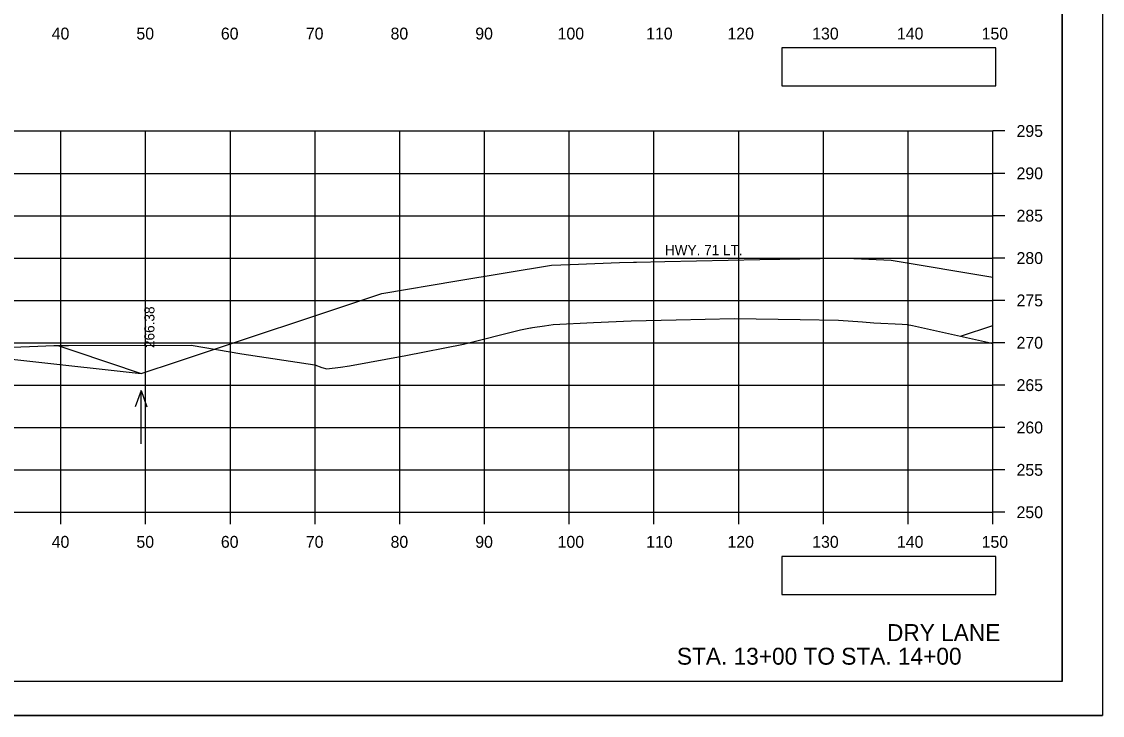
# Model space of a CAD drawing. Extents: x 285 to 4233, y -659 to 3710.
# Drawn here: x 4105.7 to 4233.3, y -365.9 to -284 of the extents above; entities that cross this region are included whole.
import ezdxf

# ---------------------------------------------------------------- set-up
doc = ezdxf.new("R2010")
doc.units = 0
for name, color, linetype in [('R_Axis', 7, 'Continuous'), ('R_Axis Annot', 7, 'Continuous'), ('R_Border', 7, 'Continuous'), ('R_Draft', 7, 'Continuous'), ('R_Exist Surface', 7, 'Continuous'), ('R_Fin Surface', 7, 'Continuous'), ('R_Grid', 7, 'Continuous'), ('R_No Plot', 7, 'Continuous'), ('R_Water', 7, 'Continuous'), ('R_Water Annot', 7, 'Continuous'), ('R_Xsect Elev', 7, 'Continuous')]:
    doc.layers.add(name, color=color, linetype=linetype)

msp = doc.modelspace()

# ---------------------------------------------------------------- linework, layer by layer
at = {"layer": 'R_Axis'}
for p, q in [((4220.38, -341.92), (4220.38, -296.92)), ((4221.78, -296.92), (4220.38, -296.92)), ((4221.78, -301.92), (4220.38, -301.92)), ((4221.78, -306.92), (4220.38, -306.92)), ((4221.78, -311.92), (4220.38, -311.92)), ((4221.78, -316.92), (4220.38, -316.92)), ((4221.78, -321.92), (4220.38, -321.92)), ((4221.78, -326.92), (4220.38, -326.92)), ((4221.78, -331.92), (4220.38, -331.92)), ((4221.78, -336.92), (4220.38, -336.92)), ((3920.38, -341.92), (4220.38, -341.92)), ((4110.38, -343.32), (4110.38, -341.92)), ((4120.38, -343.32), (4120.38, -341.92)), ((4130.38, -343.32), (4130.38, -341.92)), ((4140.38, -343.32), (4140.38, -341.92)), ((4150.38, -343.32), (4150.38, -341.92)), ((4160.38, -343.32), (4160.38, -341.92)), ((4170.38, -343.32), (4170.38, -341.92)), ((4180.38, -343.32), (4180.38, -341.92)), ((4190.38, -343.32), (4190.38, -341.92)), ((4200.38, -343.32), (4200.38, -341.92)), ((4210.38, -343.32), (4210.38, -341.92)), ((4220.38, -343.32), (4220.38, -341.92)), ((4221.78, -341.92), (4220.38, -341.92))]:
    msp.add_line(p, q, dxfattribs=at)
at = {"layer": 'R_Axis Annot'}
for points in [[(4195.48, -291.58), (4220.73, -291.58), (4220.73, -287.11), (4195.48, -287.11)], [(4195.48, -351.62), (4220.73, -351.62), (4220.73, -347.15), (4195.48, -347.15)]]:
    msp.add_lwpolyline(points, close=True, dxfattribs=at)
at = {"layer": 'R_Border'}
for q in [(4228.56, -156.46), (3912.38, -361.92)]:
    msp.add_line((4228.56, -361.92), q, dxfattribs=at)
at = {"layer": 'R_Exist Surface'}
msp.add_lwpolyline([(4099.62, -322.62), (4107.65, -322.33), (4109.55, -322.25), (4111.29, -322.25), (4125.74, -322.2), (4131.72, -323.24), (4140.36, -324.53), (4141.18, -324.83), (4141.76, -325.01), (4143.37, -324.81), (4144.46, -324.65), (4151.1, -323.41), (4157.9, -322.08), (4164.64, -320.4), (4165.8, -320.14), (4165.87, -320.14), (4166.03, -320.11), (4167.47, -319.91), (4168.47, -319.77), (4173.24, -319.54), (4177.69, -319.34), (4183.01, -319.21), (4189.83, -319.04), (4197.64, -319.18), (4202.18, -319.26), (4204.98, -319.46), (4206.32, -319.56), (4209.69, -319.74), (4210.28, -319.78), (4210.89, -319.89), (4219.77, -321.83), (4220.38, -321.99)], dxfattribs=at)
at = {"layer": 'R_Fin Surface'}
for points in [[(4110.02, -322.25), (4112.01, -322.92), (4119.87, -325.54), (4124.13, -324.12), (4148.26, -316.09), (4157.12, -314.62), (4168.3, -312.76), (4170.51, -312.67), (4176.31, -312.44), (4177.95, -312.41), (4178.31, -312.4), (4181.65, -312.33), (4192.86, -312.11), (4202.36, -311.92), (4203.12, -311.95), (4208.37, -312.16), (4220.38, -314.16)], [(4216.58, -321.14), (4220.38, -319.87)], [(4038.85, -328.34), (4060.38, -321.16), (4070.38, -320.96), (4080.38, -321.16), (4119.87, -325.54)]]:
    msp.add_lwpolyline(points, dxfattribs=at)
at = {"layer": 'R_Grid'}
for p, q in [((3920.38, -296.92), (4220.38, -296.92)), ((4110.38, -341.92), (4110.38, -296.92)), ((4120.38, -341.92), (4120.38, -296.92)), ((4130.38, -341.92), (4130.38, -296.92)), ((4140.38, -341.92), (4140.38, -296.92)), ((4150.38, -341.92), (4150.38, -296.92)), ((4160.38, -341.92), (4160.38, -296.92)), ((4170.38, -341.92), (4170.38, -296.92)), ((4180.38, -341.92), (4180.38, -296.92)), ((4190.38, -341.92), (4190.38, -296.92)), ((4200.38, -341.92), (4200.38, -296.92)), ((4210.38, -341.92), (4210.38, -296.92)), ((4220.38, -341.92), (4220.38, -296.92)), ((3920.38, -301.92), (4220.38, -301.92)), ((3920.38, -306.92), (4220.38, -306.92)), ((3920.38, -311.92), (4220.38, -311.92)), ((3920.38, -316.92), (4220.38, -316.92)), ((3920.38, -321.92), (4220.38, -321.92)), ((3920.38, -326.92), (4220.38, -326.92)), ((3920.38, -331.92), (4220.38, -331.92)), ((3920.38, -336.92), (4220.38, -336.92)), ((3920.38, -341.92), (4220.38, -341.92))]:
    msp.add_line(p, q, dxfattribs=at)
at = {"layer": 'R_No Plot'}
msp.add_line((3899.98, -365.9), (4233.31, -365.9), dxfattribs=at)
for points in [[(3899.97, -152.57), (4233.31, -152.57), (4233.31, -365.9), (3899.97, -365.9)], [(4146.3, -156.46), (4165.92, -156.46), (4165.92, -166.34), (4182.03, -166.34), (4205.23, -166.34), (4205.35, -194.5), (4228.56, -194.5), (4228.56, -361.92), (3912.38, -361.92), (3912.38, -156.46)]]:
    msp.add_lwpolyline(points, close=True, dxfattribs=at)
at = {"layer": 'R_Water Annot'}
for p, q in [((4119.84, -327.56), (4119.14, -329.48)), ((4119.84, -333.85), (4119.84, -327.56)), ((4119.84, -327.56), (4120.54, -329.48))]:
    msp.add_line(p, q, dxfattribs=at)

# ---------------------------------------------------------------- texts
at = {"layer": 'R_Axis Annot'}
for s, p in [('40', (4109.29, -286.12)), ('50', (4119.29, -286.12)), ('60', (4129.26, -286.12)), ('70', (4139.29, -286.12)), ('80', (4149.29, -286.12)), ('90', (4159.29, -286.12)), ('100', (4169.01, -286.12)), ('110', (4179.46, -286.12)), ('120', (4189.06, -286.12)), ('130', (4199.06, -286.12)), ('140', (4209.06, -286.12)), ('150', (4219.06, -286.12)), ('295', (4223.18, -297.62)), ('290', (4223.18, -302.62)), ('285', (4223.18, -307.62)), ('280', (4223.18, -312.62)), ('275', (4223.18, -317.62)), ('270', (4223.18, -322.62)), ('265', (4223.18, -327.62)), ('260', (4223.18, -332.62)), ('255', (4223.18, -337.62)), ('250', (4223.18, -342.62)), ('40', (4109.29, -346.12)), ('50', (4119.29, -346.12)), ('60', (4129.26, -346.12)), ('70', (4139.29, -346.12)), ('80', (4149.29, -346.12)), ('90', (4159.29, -346.12)), ('100', (4169.01, -346.12)), ('110', (4179.46, -346.12)), ('120', (4189.06, -346.12)), ('130', (4199.06, -346.12)), ('140', (4209.06, -346.12)), ('150', (4219.06, -346.12))]:
    msp.add_text(s, height=1.4, dxfattribs=at).set_placement(p)
at = {"layer": 'R_Draft'}
for s, p in [('DRY LANE', (4207.89, -357.13)), ('STA. 13+00 TO STA. 14+00', (4183.09, -359.92))]:
    msp.add_text(s, height=2, dxfattribs=at).set_placement(p)
at = {"layer": 'R_Water'}
msp.add_text('HWY. 71 LT.', height=1.2, dxfattribs=at).set_placement((4181.67, -311.58))
at = {"layer": 'R_Xsect Elev'}
msp.add_text('266.38', height=1.2, rotation=90, dxfattribs=at).set_placement((4121.42, -322.54))

doc.saveas('drawing.dxf')
